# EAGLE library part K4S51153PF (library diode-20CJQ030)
SAMSUNG's K4S51153PF - Y(P)F Mobile-SDRAM 8M x 16Bit x 4 Banks Mobile SDRAM in 54FBGA Organization : 32Mx16 Vdd/Vddq : 1.8V / 1.8V Icc1/Icc6 : ~55mA/~600uA Speed : 133MHz, CL3; 111MHz,CL3; 105MHz,CL3/CL2 Features: VDD/VDDQ =1.8V/1.8V. LVCMOS compatible with multiplexed address. Four banks operation. MRS cycle with address key programs. -. CAS latency (1, 2 & 3). -. Burst length (1, 2, 4, 8 & Full page). -. Burst type (Sequential & Interleave). EMRS cycle with address key programs. All inputs are sampled at the positive going edge of the system clock. Burst read single-bit write operation. Special Function Support. -. PASR (Partial Array Self Refresh). -. Internal TCSR (Temperature Compensated Self Refresh) -. DS (Driver Strength) DQM for masking. Auto refresh. 64ms refresh period (8K cycle). Commercial Temperature Operation (-25°C ~ 70°C). 2 /CS Support. 54Balls FBGA( -YXXX -Pb, -PXXX -Pb Free). Description: The K4S51153PF is 536,870,912 bits synchronous high data rate Dynamic RAM organized as 4 x 8,388,608 words by 16 bits, fabricated with SAMSUNG's high performance CMOS technology. Synchronous design allows precise cycle control with the use of system clock and I/O transactions are possible on every clock cycle. Range of operating frequencies, programmable burst lengths and programmable latencies allow the same device to be useful for a variety of high bandwidth and high performance memory system applications. Please send any comments to: messi@users.sourceforge.net
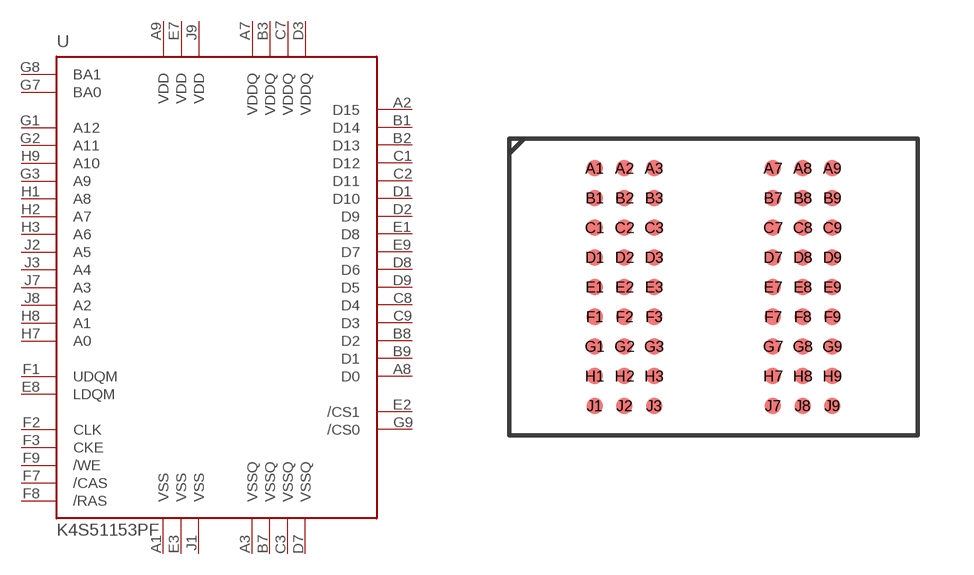
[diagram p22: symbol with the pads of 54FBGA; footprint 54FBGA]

Designator prefix U

## K4S51153PF  [54FBGA]
A1  VSS  pwr
A2  D15
A3  VSSQ  pwr
A7  VDDQ  pwr
A8  D0
A9  VDD  pwr
B1  D14
B2  D13
B3  VDDQ  pwr
B7  VSSQ  pwr
B8  D2
B9  D1
C1  D12
C2  D11
C3  VSSQ  pwr
C7  VDDQ  pwr
C8  D4
C9  D3
D1  D10
D2  D9
D3  VDDQ  pwr
D7  VSSQ  pwr
D8  D6
D9  D5
E1  D8
E2  /CS1
E3  VSS  pwr
E7  VDD  pwr
E8  LDQM
E9  D7
F1  UDQM
F2  CLK
F3  CKE
F7  /CAS
F8  /RAS
F9  /WE
G1  A12
G2  A11
G3  A9
G7  BA0
G8  BA1
G9  /CS0
H1  A8
H2  A7
H3  A6
H7  A0
H8  A1
H9  A10
J1  VSS  pwr
J2  A5
J3  A4
J7  A3
J8  A2
J9  VDD  pwr

## Footprint 54FBGA (pad centres in mm)
54 PIN FBGA Pitch: 0.8mm balldiameter 0.5mm Please send any comments to: messi@users.sourceforge.net
smd 0.45 x 0.45: A1 -3.2,3.2; A2 -2.4,3.2; A3 -1.6,3.2; A7 1.6,3.2; A8 2.4,3.2; A9 3.2,3.2; B1 -3.2,2.4; B2 -2.4,2.4; B3 -1.6,2.4; B7 1.6,2.4; B8 2.4,2.4; B9 3.2,2.4; C1 -3.2,1.6; C2 -2.4,1.6; C3 -1.6,1.6; C7 1.6,1.6; C8 2.4,1.6; C9 3.2,1.6; D1 -3.2,0.8; D2 -2.4,0.8; D3 -1.6,0.8; D7 1.6,0.8; D8 2.4,0.8; D9 3.2,0.8; E1 -3.2,0; E2 -2.4,0; E3 -1.6,0; E7 1.6,0; E8 2.4,0; E9 3.2,0; F1 -3.2,-0.8; F2 -2.4,-0.8; F3 -1.6,-0.8; F7 1.6,-0.8; F8 2.4,-0.8; F9 3.2,-0.8; G1 -3.2,-1.6; G2 -2.4,-1.6; G3 -1.6,-1.6; G7 1.6,-1.6; G8 2.4,-1.6; G9 3.2,-1.6; H1 -3.2,-2.4; H2 -2.4,-2.4; H3 -1.6,-2.4; H7 1.6,-2.4; H8 2.4,-2.4; H9 3.2,-2.4; J1 -3.2,-3.2; J2 -2.4,-3.2; J3 -1.6,-3.2; J7 1.6,-3.2; J8 2.4,-3.2; J9 3.2,-3.2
